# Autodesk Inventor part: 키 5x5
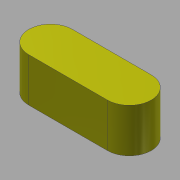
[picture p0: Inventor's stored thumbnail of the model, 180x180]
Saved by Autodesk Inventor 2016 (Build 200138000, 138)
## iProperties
Created: 2016-04
Part Number: 키 5x5
Document SubType Name: Modeling
Designer: mdu
Density: 7.86 g/cm^3
Mass: 2.54015 g
Surface Area: 2.9781 cm^2
Volume: 0.323175 cm^3
Material: 강철, 연강
Appearance: 강철 - 광택
Author: mdu
Revision Number: 1
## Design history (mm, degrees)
sketch "스케치1"
  geometry: L1 (-4.5, -2.5)-(4.5, -2.5); L2 (4.5, 2.5)-(-4.5, 2.5); A1 r 2.5 centre (4.5, 0) between (4.5, -2.5) and (4.5, 2.5); A2 r 2.5 centre (-4.5, 0) between (-4.5, 2.5) and (-4.5, -2.5); 2 further points
  constraints: 4 end point, 4 point on circle, 4 tangent, 2 centre point, 1 horizontal, 1 horizontal alignment, 1 midpoint, 1 parallel, 1 vertical alignment
  dimensions: "d0" = 5 distance between parallel lines of L1 L2; "d1" = 14 dimension on A1 A2
extrude "돌출1" new body sketch "스케치1" stored distance "d2" = 5; taper "d3" = 0 deg
node "솔리드1"
